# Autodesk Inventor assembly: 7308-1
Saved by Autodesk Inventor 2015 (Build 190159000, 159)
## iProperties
Created: 2021-01
Part Number: 7308-1
Checked By: TraceParts S.A.
Catalog Web Link: www.traceparts.com
Document SubType Name: Assembly
Designer: TraceParts
Company: TraceParts S.A.
Author: TraceParts
SUPPLIER_NAME: RS Components
SUPPLIER: RS Pro
DESIGN: RS PRO Slotted Panel Trunking Grey, Open Slot, W30 mm x D30mm, L2m PVC
REFERENCE: 7308-1
Buy_Now: https://uk.rs-online.com/web/p/products/1369102?cm_mmc=en-ds-_-mcad-_-traceparts-_-1369102'
rs_stock_number: 1369102
TraceParts.PartVersion: 1.0.3
TraceParts.PartStatus: Published
TraceParts.PartNumber: 10-22112017-067131
TraceParts.PartLanguage: en
TraceParts.InstanceId: 10-22112017-067131EP51HF6IA9D36B1ALOM88AF4N
TraceParts.PartTitle: RS PRO Slotted Panel Trunking Grey, Open Slot, W30 mm x D30mm, L2m PVC
TRACEPARTS: TRACEPARTS
TraceParts.ClassPath: RS_COMPONENTS:10-22112017-067131
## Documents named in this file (3)
- C:\TPO v2\SharedFS\Outgoing\7308-1.iam
- C:\TPO v2\SharedFS\Outgoing\7308-1_01.ipt
- C:\TPO v2\SharedFS\Outgoing\7308-1_02.ipt
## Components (2 placed, 2 different names)
1. 7308-1_01:1
2. 7308-1_02:1
